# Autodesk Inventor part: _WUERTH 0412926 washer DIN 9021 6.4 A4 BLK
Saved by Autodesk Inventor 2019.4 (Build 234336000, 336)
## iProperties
Created: 2021-06
Part Number: _WUERTH 0412926 washer DIN 9021 6.4 A4 BLK
Material: Generic
Document SubType Name: Modeling
Designer: Administrator
Density: 1 g/cm^3
Appearance: Default
Title: _WUERTH 0412926 washer DIN 9021 6.4 A4 BLK
Author: Administrator
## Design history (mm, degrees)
feature "Body1"
body "Solid1"
